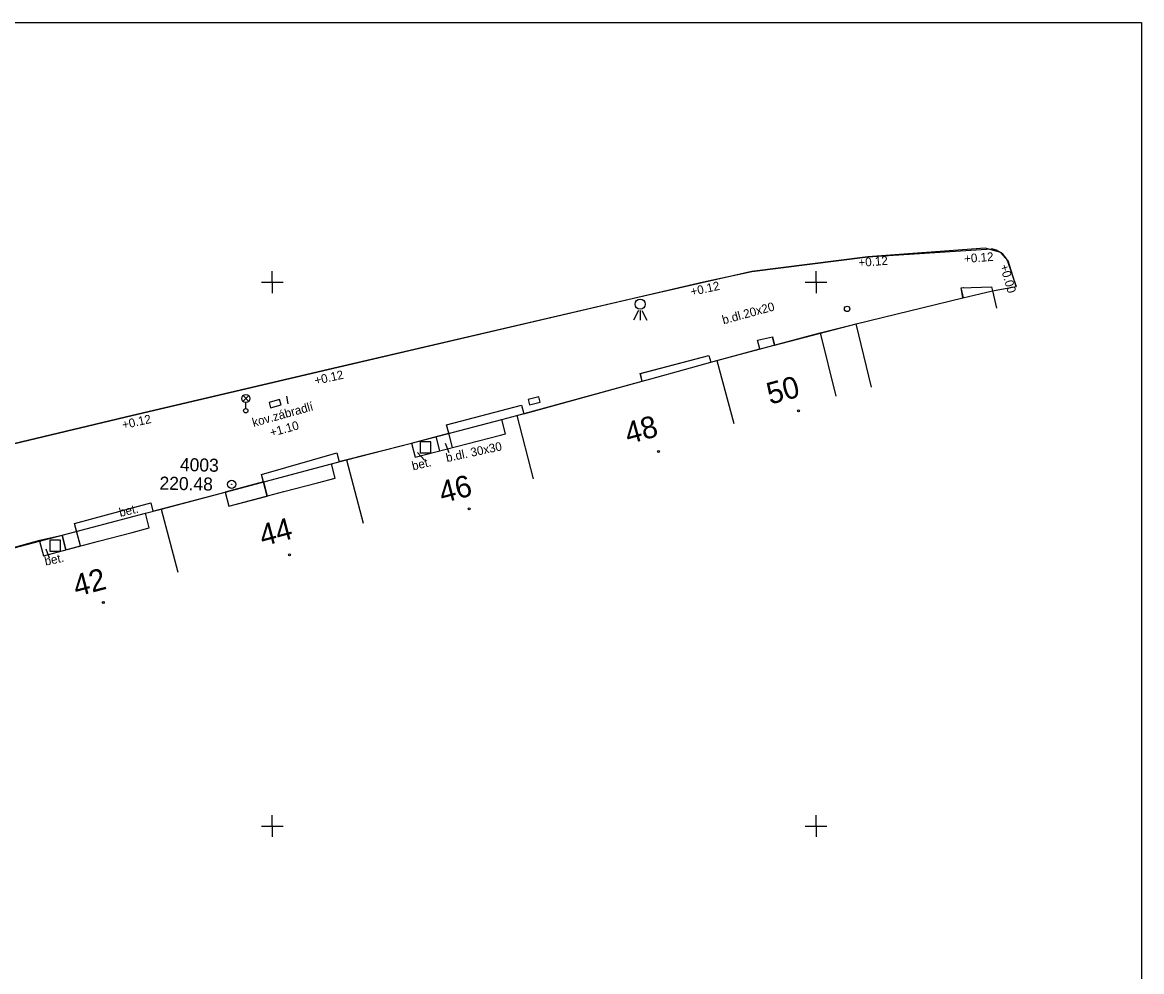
# Model space of a CAD drawing. Extents: x -598468 to -598310, y -1159412 to -1159338.
# Drawn here: x -598361.5 to -598310, y -1159381.7 to -1159338.1 of the extents above; entities that cross this region are included whole.
import ezdxf

# ---------------------------------------------------------------- set-up
doc = ezdxf.new("R2010")
doc.units = 0
for name, color, linetype in [('Vrstva 1', 7, 'Continuous'), ('Vrstva 15', 7, 'Continuous'), ('Vrstva 2', 7, 'Continuous'), ('Vrstva 22', 7, 'Continuous'), ('Vrstva 23', 7, 'Continuous'), ('Vrstva 29', 7, 'Continuous'), ('Vrstva 34', 7, 'Continuous'), ('Vrstva 4', 7, 'Continuous'), ('Vrstva 43', 7, 'Continuous'), ('Vrstva 44', 7, 'Continuous'), ('Vrstva 49', 7, 'Continuous'), ('Vrstva 5', 7, 'Continuous'), ('Vrstva 50', 7, 'Continuous'), ('Vrstva 62', 7, 'Continuous'), ('Vrstva 63', 7, 'Continuous'), ('Vrstva 7', 7, 'Continuous')]:
    doc.layers.add(name, color=color, linetype=linetype)

msp = doc.modelspace()

# ---------------------------------------------------------------- linework, layer by layer
at = {"layer": 'Vrstva 1'}
for p, q in [((-598362.533, -1159338.058), (-598310.033, -1159338.058)), ((-598310.033, -1159338.058), (-598310.033, -1159412.308))]:
    msp.add_line(p, q, dxfattribs=at)
at = {"layer": 'Vrstva 15'}
for centre in [(-598325.8059, -1159355.9159), (-598332.2459, -1159357.7889), (-598340.9519, -1159360.4169), (-598349.2079, -1159362.5339), (-598357.7699, -1159364.7309)]:
    msp.add_circle(centre, 0.0438, dxfattribs=at)
at = {"layer": 'Vrstva 2'}
for radius in [0.1875, 0.00896]:
    msp.add_circle((-598351.868, -1159359.294), radius, dxfattribs=at)
at = {"layer": 'Vrstva 22'}
msp.add_lwpolyline([(-598349.272, -1159355.595), (-598349.331, -1159355.244)], dxfattribs=at)
at = {"layer": 'Vrstva 23'}
for p, q in [((-598342.705, -1159357.341), (-598343.205, -1159357.341)), ((-598343.205, -1159357.341), (-598343.205, -1159357.841)), ((-598342.705, -1159357.841), (-598342.705, -1159357.341)), ((-598343.205, -1159357.841), (-598342.705, -1159357.841)), ((-598359.734, -1159361.859), (-598360.234, -1159361.859)), ((-598360.234, -1159361.859), (-598360.234, -1159362.359)), ((-598359.734, -1159362.359), (-598359.734, -1159361.859)), ((-598360.234, -1159362.359), (-598359.734, -1159362.359))]:
    msp.add_line(p, q, dxfattribs=at)
msp.add_circle((-598323.573, -1159351.227), 0.125, dxfattribs=at)
at = {"layer": 'Vrstva 29'}
for p, q in [((-598351.351, -1159355.479), (-598351.087, -1159355.215)), ((-598351.083, -1159355.478), (-598351.347, -1159355.213)), ((-598351.219, -1159355.81), (-598351.219, -1159355.535))]:
    msp.add_line(p, q, dxfattribs=at)
for centre, radius in [((-598351.219, -1159355.3475), 0.1875), ((-598351.219, -1159355.91), 0.1)]:
    msp.add_circle(centre, radius, dxfattribs=at)
at = {"layer": 'Vrstva 34'}
for points in [[(-598350.08, -1159355.776), (-598349.6, -1159355.636), (-598349.67, -1159355.396), (-598350.15, -1159355.536)], [(-598338.173, -1159355.633), (-598337.689, -1159355.509), (-598337.751, -1159355.267), (-598338.235, -1159355.391)]]:
    msp.add_lwpolyline(points, close=True, dxfattribs=at)
at = {"layer": 'Vrstva 4'}
for p, q in [((-598318.219, -1159350.249), (-598318.211, -1159350.239)), ((-598352.944, -1159359.868), (-598352.944, -1159359.866)), ((-598352.944, -1159359.867), (-598352.944, -1159359.868))]:
    msp.add_line(p, q, dxfattribs=at)
for points in [[(-598318.223, -1159350.719), (-598318.332, -1159350.266), (-598316.941, -1159350.209), (-598316.896, -1159350.399)], [(-598322.457, -1159354.828), (-598323.161, -1159351.912), (-598318.253, -1159350.727)], [(-598317.475, -1159350.539), (-598316.896, -1159350.399), (-598316.703, -1159351.199)], [(-598329.558, -1159353.606), (-598324.817, -1159352.323), (-598324.094, -1159355.235)], [(-598324.817, -1159352.323), (-598323.161, -1159351.912)], [(-598332.994, -1159354.55), (-598333.078, -1159354.206), (-598329.927, -1159353.375), (-598329.842, -1159353.684)], [(-598331.056, -1159354.018), (-598329.558, -1159353.606), (-598328.774, -1159356.502)], [(-598338.76, -1159356.135), (-598332.994, -1159354.55), (-598332.602, -1159354.442)], [(-598341.715, -1159357.601), (-598341.885, -1159356.949), (-598341.985, -1159356.563), (-598338.539, -1159355.659), (-598338.433, -1159356.045)], [(-598343.603, -1159357.397), (-598339.451, -1159356.315)], [(-598339.51, -1159357.026), (-598339.279, -1159356.966), (-598339.451, -1159356.315), (-598338.76, -1159356.135), (-598338.004, -1159359.038)], [(-598346.585, -1159358.173), (-598343.603, -1159357.397), (-598343.434, -1159358.048), (-598341.059, -1159357.429)], [(-598350.403, -1159359.184), (-598350.495, -1159358.838), (-598347.039, -1159357.846), (-598346.928, -1159358.264)], [(-598352.164, -1159359.65), (-598347.276, -1159358.356)], [(-598347.919, -1159359.22), (-598347.104, -1159359.004), (-598347.276, -1159358.356), (-598346.585, -1159358.173), (-598345.829, -1159361.076)], [(-598350.403, -1159359.184), (-598352.164, -1159359.65)], [(-598350.403, -1159359.184), (-598350.231, -1159359.832)], [(-598355.104, -1159360.428), (-598352.164, -1159359.65), (-598351.993, -1159360.298), (-598349.465, -1159359.629)], [(-598360.699, -1159361.901), (-598355.834, -1159360.62)], [(-598358.821, -1159362.127), (-598358.999, -1159361.453), (-598359.093, -1159361.098), (-598355.588, -1159360.147), (-598355.487, -1159360.529)], [(-598356.442, -1159361.501), (-598355.656, -1159361.294), (-598355.834, -1159360.62), (-598355.104, -1159360.428), (-598354.34, -1159363.329)], [(-598362.859, -1159365.571), (-598363.626, -1159362.671), (-598360.699, -1159361.901), (-598360.522, -1159362.575), (-598357.992, -1159361.909)]]:
    msp.add_lwpolyline(points, dxfattribs=at)
at = {"layer": 'Vrstva 44'}
for p, q in [((-598333.163, -1159351.302), (-598333.389, -1159351.754)), ((-598333.089, -1159351.304), (-598333.089, -1159351.754)), ((-598333.014, -1159351.302), (-598332.789, -1159351.754))]:
    msp.add_line(p, q, dxfattribs=at)
msp.add_circle((-598333.089, -1159351.009), 0.234, dxfattribs=at)
at = {"layer": 'Vrstva 49'}
for points in [[(-598341.874, -1159357.852), (-598342.039, -1159357.423)], [(-598343.005, -1159358.177), (-598343.32, -1159357.836)], [(-598360.246, -1159362.681), (-598360.406, -1159362.269)]]:
    msp.add_lwpolyline(points, dxfattribs=at)
at = {"layer": 'Vrstva 5'}
for points in [[(-598318.253, -1159350.727), (-598317.475, -1159350.539)], [(-598332.602, -1159354.442), (-598331.056, -1159354.018)], [(-598341.059, -1159357.429), (-598339.51, -1159357.026)], [(-598349.465, -1159359.629), (-598347.919, -1159359.22)], [(-598357.992, -1159361.909), (-598356.442, -1159361.501)]]:
    msp.add_lwpolyline(points, dxfattribs=at)
at = {"layer": 'Vrstva 62'}
for p, q in [((-598350, -1159350), (-598350, -1159349.5)), ((-598325, -1159350), (-598325, -1159349.5)), ((-598350.5, -1159350), (-598350, -1159350)), ((-598350, -1159350), (-598349.5, -1159350)), ((-598350, -1159350), (-598350, -1159350.5)), ((-598325.5, -1159350), (-598325, -1159350)), ((-598325, -1159350), (-598324.5, -1159350)), ((-598325, -1159350), (-598325, -1159350.5)), ((-598350, -1159375), (-598350, -1159374.5)), ((-598325, -1159375), (-598325, -1159374.5)), ((-598350.5, -1159375), (-598350, -1159375)), ((-598350, -1159375), (-598349.5, -1159375)), ((-598350, -1159375), (-598350, -1159375.5)), ((-598325.5, -1159375), (-598325, -1159375)), ((-598325, -1159375), (-598324.5, -1159375)), ((-598325, -1159375), (-598325, -1159375.5))]:
    msp.add_line(p, q, dxfattribs=at)
at = {"layer": 'Vrstva 63'}
msp.add_lwpolyline([(-598364.012, -1159362.773), (-598360.694, -1159361.854), (-598359.67, -1159361.63), (-598359.493, -1159362.304), (-598358.821, -1159362.127), (-598359.093, -1159361.098), (-598355.588, -1159360.147), (-598355.487, -1159360.529), (-598352.164, -1159359.65), (-598351.993, -1159360.298), (-598350.231, -1159359.832), (-598350.495, -1159358.838), (-598347.039, -1159357.846), (-598346.928, -1159358.264), (-598346.939, -1159358.242), (-598343.603, -1159357.397), (-598341.885, -1159356.949), (-598341.985, -1159356.563), (-598338.539, -1159355.659), (-598338.433, -1159356.045), (-598332.994, -1159354.55), (-598333.091, -1159354.198), (-598329.927, -1159353.375), (-598329.842, -1159353.684), (-598327.586, -1159353.072), (-598327.696, -1159352.665), (-598327.011, -1159352.516), (-598326.91, -1159352.889), (-598323.161, -1159351.912), (-598318.253, -1159350.727), (-598318.332, -1159350.266), (-598316.941, -1159350.209), (-598316.896, -1159350.399), (-598315.806, -1159350.201), (-598316.173, -1159349.022), (-598316.499, -1159348.634), (-598317.219, -1159348.442), (-598322.621, -1159348.841), (-598327.958, -1159349.509), (-598333.786, -1159350.84), (-598347.429, -1159354.018), (-598356.442, -1159356.127), (-598364.611, -1159358.068)], dxfattribs=at)
at = {"layer": 'Vrstva 7'}
for p, q in [((-598327.586, -1159353.072), (-598327.696, -1159352.665)), ((-598326.91, -1159352.889), (-598327.011, -1159352.516)), ((-598342.296, -1159357.751), (-598342.466, -1159357.101)), ((-598359.493, -1159362.304), (-598359.67, -1159361.63))]:
    msp.add_line(p, q, dxfattribs=at)
for points in [[(-598460.606, -1159380.951), (-598440.32, -1159376.125), (-598425.303, -1159372.541), (-598424.365, -1159372.319), (-598420.776, -1159371.464), (-598419.837, -1159371.24), (-598416.865, -1159370.534), (-598415.902, -1159370.301), (-598412.459, -1159369.48), (-598411.487, -1159369.252), (-598399.215, -1159366.328), (-598381.966, -1159362.196), (-598373.433, -1159360.163), (-598364.611, -1159358.068), (-598356.442, -1159356.127), (-598347.429, -1159354.018), (-598330.181, -1159349.984), (-598327.958, -1159349.509), (-598322.621, -1159348.841), (-598316.937, -1159348.463)], [(-598316.193, -1159349.028), (-598315.806, -1159350.201)], [(-598316.896, -1159350.399), (-598315.806, -1159350.201)], [(-598327.696, -1159352.665), (-598327.011, -1159352.516)], [(-598360.699, -1159361.901), (-598359.67, -1159361.63)]]:
    msp.add_lwpolyline(points, dxfattribs=at)
msp.add_arc((-598317.1069, -1159349.4591), 1.0105, 25.25466, 80.31864, dxfattribs=at)

# ---------------------------------------------------------------- texts
at = {"layer": 'Vrstva 2'}
for s, p in [('4003', (-598354.253, -1159358.682)), ('220.48', (-598355.193, -1159359.535))]:
    msp.add_text(s, height=0.6, rotation=358.83821, dxfattribs=at).set_placement(p)
at = {"layer": 'Vrstva 43'}
for s, height, rotation, p in [('50', 1, 15.14257, (-598327.116, -1159355.634)), ('48', 1, 15.37236, (-598333.634, -1159357.456)), ('46', 1, 14.58645, (-598342.186, -1159360.169)), ('44', 1, 14.82219, (-598350.442, -1159362.151)), ('42', 0.99998, 14.73874, (-598359.007, -1159364.465))]:
    msp.add_text(s, height=height, rotation=rotation, dxfattribs=at).set_placement(p)
at = {"layer": 'Vrstva 49'}
for s, height, rotation, p in [('b.dl.20x20', 0.39995, 15.26063, (-598329.257, -1159351.941)), ('kov.zábradlí', 0.399996, 15.55988, (-598350.863, -1159356.657)), ('+1.10', 0.4, 15.55988, (-598350.048, -1159357.117)), ('b.dl. 30x30', 0.399942, 12.1161, (-598341.974, -1159358.273)), ('bet.', 0.4, 13.35082, (-598343.532, -1159358.653)), ('bet.', 0.4, 13.35082, (-598356.993, -1159360.792)), ('bet.', 0.4, 12.27565, (-598360.427, -1159363.034))]:
    msp.add_text(s, height=height, rotation=rotation, dxfattribs=at).set_placement(p)
at = {"layer": 'Vrstva 50'}
for s, rotation, p in [('+0.12', 4.29919, (-598318.18, -1159349.12)), ('+0.12', 4.29919, (-598323.037, -1159349.301)), ('+0.00', 286.29609, (-598316.554, -1159349.242)), ('+0.12', 12.61431, (-598330.723, -1159350.64)), ('+0.12', 12.61431, (-598348.016, -1159354.724)), ('+0.12', 12.61431, (-598356.86, -1159356.762))]:
    msp.add_text(s, height=0.4, rotation=rotation, dxfattribs=at).set_placement(p)

doc.saveas('drawing.dxf')
